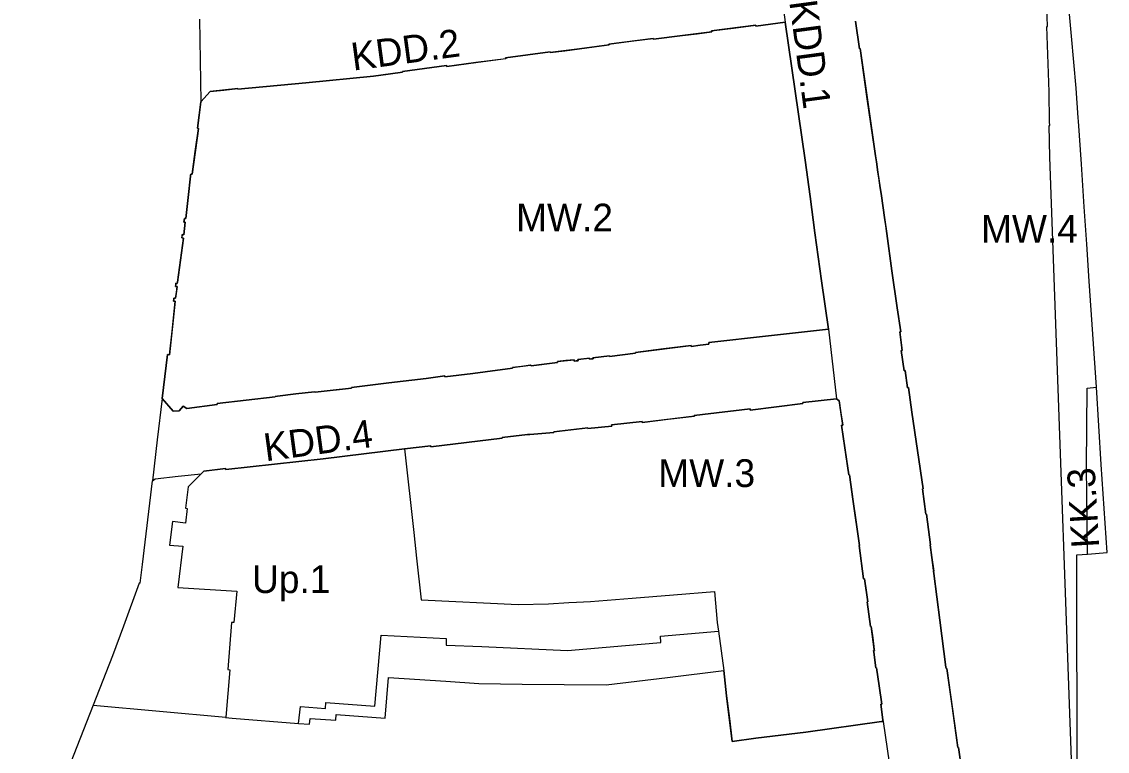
# Model space of a CAD drawing. Extents: x 7423893 to 7425332, y 5547241 to 5548246.
# Drawn here: x 7424450.7 to 7424646.4, y 5547880.1 to 5548011.5 of the extents above; entities that cross this region are included whole.
import ezdxf

# ---------------------------------------------------------------- set-up
doc = ezdxf.new("R2010")
doc.units = 0
for name, color, linetype in [('linie rozgraniczające', 7, 'Continuous'), ('nieprzekraczalne linie zabudowy', 7, 'Continuous'), ('obowiazujace linie zabudowy', 7, 'Continuous'), ('przeznaczenia terenów', 7, 'Continuous')]:
    doc.layers.add(name, color=color, linetype=linetype)

msp = doc.modelspace()

# ---------------------------------------------------------------- linework, layer by layer
at = {"layer": 'linie rozgraniczające'}
for p, q in [((7424586.51, 5548024.42), (7424588.29, 5548011.39)), ((7424596.1, 5547956.13), (7424597.56, 5547943.58))]:
    msp.add_line(p, q, dxfattribs=at)
for points in [[(7424641.11, 5547994.19), (7424640.74, 5547999.53), (7424639.91, 5548008.88), (7424639.08, 5548018.22)], [(7424482.78, 5548011.96), (7424482.88, 5548004.5), (7424482.99, 5547997.04)], [(7424588.29, 5548011.39), (7424590.09, 5547998.96), (7424591.9, 5547986.54), (7424592.79, 5547980), (7424593.67, 5547973.47), (7424594.88, 5547964.8), (7424596.1, 5547956.13), (7424585.32, 5547954.92), (7424574.54, 5547953.71), (7424574.57, 5547953.41), (7424572.98, 5547953.21), (7424571.39, 5547953.01), (7424571.37, 5547953.16), (7424566.35, 5547952.54), (7424561.33, 5547951.92), (7424561.34, 5547951.85), (7424561.35, 5547951.78), (7424559.01, 5547951.49), (7424556.67, 5547951.2), (7424556.66, 5547951.29), (7424555.17, 5547951.13), (7424553.67, 5547950.97), (7424553.68, 5547950.88), (7424553.69, 5547950.79), (7424553.38, 5547950.75), (7424553.07, 5547950.72), (7424553.06, 5547950.81), (7424553.05, 5547950.9), (7424552, 5547950.79), (7424550.96, 5547950.67), (7424550.99, 5547950.43), (7424550.64, 5547950.39), (7424550.29, 5547950.35), (7424550.26, 5547950.59), (7424548.77, 5547950.44), (7424547.27, 5547950.28), (7424547.3, 5547950.08), (7424544.9, 5547949.79), (7424542.5, 5547949.49), (7424542.48, 5547949.6), (7424542.43, 5547949.6), (7424540.79, 5547949.4), (7424539.14, 5547949.19), (7424539.15, 5547949.06), (7424534.22, 5547948.42), (7424531.99, 5547948.14), (7424526.97, 5547947.53), (7424526.95, 5547947.68), (7424523.63, 5547947.25), (7424516.9, 5547946.43), (7424510.16, 5547945.61), (7424510.17, 5547945.51), (7424506.87, 5547945.12), (7424503.57, 5547944.73), (7424503.49, 5547944.82), (7424500.13, 5547944.43), (7424496.78, 5547944.04), (7424496.4, 5547944), (7424496.41, 5547943.94), (7424491.17, 5547943.32), (7424485.94, 5547942.69), (7424485.96, 5547942.53), (7424480.46, 5547941.83), (7424479.8, 5547942.21), (7424479.08, 5547941.42), (7424478.01, 5547941.35), (7424476.01, 5547943.62)], [(7424482.99, 5547997.04), (7424484.67, 5547998.89), (7424487.16, 5547999.17), (7424489.64, 5547999.46), (7424489.66, 5547999.3), (7424501.9, 5548000.49), (7424514.13, 5548001.67), (7424516.75, 5548002.01), (7424519.36, 5548002.36), (7424519.34, 5548002.52), (7424523.31, 5548003.04), (7424527.28, 5548003.57), (7424527.3, 5548003.42), (7424532.56, 5548004.11), (7424537.94, 5548004.82), (7424537.92, 5548004.97), (7424541.92, 5548005.51), (7424545.93, 5548006.05), (7424545.95, 5548005.9), (7424548.6, 5548006.25), (7424551.25, 5548006.59), (7424553.91, 5548006.94), (7424556.56, 5548007.29), (7424556.54, 5548007.43), (7424560.54, 5548007.94), (7424564.53, 5548008.45), (7424564.55, 5548008.3), (7424569.81, 5548008.98), (7424572.44, 5548009.32), (7424575.06, 5548009.66), (7424575.04, 5548009.82), (7424579.02, 5548010.34), (7424582.99, 5548010.86), (7424583.01, 5548010.7), (7424588.29, 5548011.39)], [(7424620.66, 5547872.83), (7424619.56, 5547880.75), (7424619.45, 5547880.74), (7424618.46, 5547887.87), (7424617.47, 5547895), (7424617.31, 5547894.98), (7424617.27, 5547895.26), (7424616.19, 5547903.69), (7424616.19, 5547903.69), (7424615.1, 5547912.11), (7424615.05, 5547912.5), (7424615.07, 5547912.5), (7424615.08, 5547912.51), (7424615.06, 5547912.68), (7424614.75, 5547914.98), (7424614.45, 5547917.28), (7424614.49, 5547917.29), (7424614.52, 5547917.29), (7424614.15, 5547920.03), (7424613.77, 5547922.77), (7424613.72, 5547922.76), (7424613.67, 5547922.76), (7424613.04, 5547927.35), (7424613.2, 5547927.38), (7424611.11, 5547941.13), (7424610.52, 5547945.58), (7424610.38, 5547945.57), (7424609.93, 5547948.64), (7424609.76, 5547948.62), (7424609.24, 5547952.27), (7424609.42, 5547952.29), (7424608.98, 5547955.6), (7424609.14, 5547955.62), (7424608.47, 5547959.96), (7424607.54, 5547966.63), (7424606.62, 5547973.31), (7424606.42, 5547974.74), (7424606.26, 5547975.81), (7424605.58, 5547980.54), (7424605.43, 5547981.54), (7424605.17, 5547983.37), (7424605.02, 5547984.39), (7424604.74, 5547986.24), (7424604.6, 5547987.32), (7424604.42, 5547988.59), (7424603.11, 5547997.61), (7424601.8, 5548006.62), (7424601.7, 5548006.6), (7424600.96, 5548011.55)], [(7424476.01, 5547943.62), (7424477.01, 5547951.52), (7424477.35, 5547951.48), (7424477.87, 5547956.31), (7424478.38, 5547961.14), (7424478.24, 5547961.16), (7424478.09, 5547961.17), (7424478.12, 5547961.44), (7424478.15, 5547961.71), (7424478.29, 5547961.7), (7424478.44, 5547961.68), (7424478.58, 5547962.72), (7424478.71, 5547963.76), (7424478.58, 5547963.78), (7424478.44, 5547963.79), (7424478.46, 5547964.08), (7424478.49, 5547964.36), (7424478.61, 5547964.34), (7424478.73, 5547964.32), (7424478.77, 5547964.57), (7424479.31, 5547968.54), (7424479.85, 5547972.52), (7424479.71, 5547972.54), (7424479.57, 5547972.56), (7424479.61, 5547972.86), (7424479.64, 5547973.15), (7424479.78, 5547973.13), (7424479.92, 5547973.12), (7424480.05, 5547974.24), (7424480.19, 5547975.36), (7424480.07, 5547975.38), (7424479.94, 5547975.39), (7424479.98, 5547975.71), (7424480.02, 5547976.04), (7424480.15, 5547976.03), (7424480.27, 5547976.01), (7424480.7, 5547979.83), (7424481.13, 5547983.66), (7424481.16, 5547983.84), (7424481.18, 5547984.03), (7424481.3, 5547984.01), (7424481.43, 5547984), (7424482, 5547988.13), (7424482.56, 5547992.26), (7424482.46, 5547992.27), (7424482.37, 5547992.28), (7424482.68, 5547994.66), (7424482.99, 5547997.04)], [(7424640.9, 5547851.91), (7424640.96, 5547859.51), (7424641.01, 5547867.11), (7424640.96, 5547875.45), (7424640.92, 5547883.78), (7424640.91, 5547890.83), (7424640.89, 5547897.87), (7424640.87, 5547906.66), (7424640.85, 5547915.45), (7424642.77, 5547915.6), (7424646.36, 5547915.88), (7424645.82, 5547923.81), (7424645.28, 5547931.74), (7424644.86, 5547938.7), (7424644.43, 5547945.66), (7424643.77, 5547955.2), (7424643.1, 5547964.73), (7424642.66, 5547971.42), (7424642.22, 5547978.12), (7424641.69, 5547985.83), (7424641.15, 5547993.55), (7424641.11, 5547994.19)], [(7424642.77, 5547915.6), (7424642.61, 5547931.44), (7424642.76, 5547945.46), (7424644.43, 5547945.66)], [(7424476.01, 5547943.62), (7424475.14, 5547936.2), (7424474.27, 5547928.77)], [(7424474.27, 5547928.77), (7424474.74, 5547929.16), (7424478.89, 5547929.61), (7424483.04, 5547930.06), (7424483.51, 5547930.53), (7424487.46, 5547931.01), (7424487.49, 5547930.82), (7424505.04, 5547932.74), (7424519.71, 5547934.58), (7424524.45, 5547935.07), (7424524.46, 5547934.93), (7424530.89, 5547935.7), (7424537.32, 5547936.46), (7424537.31, 5547936.57), (7424541.84, 5547937.13), (7424541.98, 5547937.13), (7424542.29, 5547937.14), (7424546.6, 5547937.48), (7424546.59, 5547937.63), (7424552.75, 5547938.34), (7424552.76, 5547938.19), (7424557.05, 5547938.66), (7424557.04, 5547938.75), (7424557.02, 5547938.85), (7424562.52, 5547939.47), (7424562.53, 5547939.32), (7424567.24, 5547939.87), (7424571.95, 5547940.41), (7424571.93, 5547940.58), (7424577.44, 5547941.2), (7424577.99, 5547941.25), (7424579.99, 5547941.49), (7424581.99, 5547941.73), (7424582.02, 5547941.54), (7424586.77, 5547942.13), (7424591.51, 5547942.72), (7424591.49, 5547942.88), (7424597.56, 5547943.58), (7424598.03, 5547943.22), (7424598.35, 5547941.03), (7424598.67, 5547938.83), (7424598.47, 5547938.8), (7424599.12, 5547934.33), (7424599.76, 5547929.86), (7424599.9, 5547929.88), (7424600.21, 5547927.69), (7424600.53, 5547925.5), (7424601.12, 5547921.33), (7424601.72, 5547917.17), (7424601.62, 5547917.15), (7424602.45, 5547911.15), (7424602.63, 5547911.17), (7424602.91, 5547909.09), (7424603.18, 5547907.02), (7424603.13, 5547907.01), (7424603.08, 5547907), (7424603.38, 5547904.76), (7424603.67, 5547902.53), (7424603.75, 5547902.54), (7424603.82, 5547902.55), (7424604.08, 5547900.49), (7424604.35, 5547898.42), (7424604.38, 5547898.23), (7424604.23, 5547898.21), (7424604.26, 5547897.95), (7424604.45, 5547896.53), (7424604.63, 5547895.11), (7424604.78, 5547895.13), (7424605.25, 5547891.86), (7424605.72, 5547888.58), (7424605.56, 5547888.56), (7424605.93, 5547885.74), (7424605.97, 5547885.46)], [(7424519.71, 5547934.58), (7424521.37, 5547919.51), (7424521.87, 5547914.86), (7424522.72, 5547907.35), (7424540.2, 5547906.53), (7424545.64, 5547906.65), (7424549.3, 5547906.86), (7424550.69, 5547906.94), (7424553.24, 5547907.09), (7424560.72, 5547907.68), (7424568.15, 5547908.26), (7424575.58, 5547908.85), (7424576.06, 5547903.26), (7424576.26, 5547901.72), (7424576.75, 5547898.19), (7424577.23, 5547894.65)], [(7424472.03, 5547910.35), (7424472.22, 5547911.83), (7424472.46, 5547913.75), (7424474.27, 5547928.77)], [(7424472.03, 5547910.35), (7424471.85, 5547910.38), (7424469.05, 5547902.62), (7424467.1, 5547897.3), (7424450.71, 5547855.6)], [(7424463.6, 5547888.39), (7424487.47, 5547886.26), (7424487.46, 5547886.16), (7424488.65, 5547886.07), (7424500.61, 5547885.12), (7424502.6, 5547884.96), (7424502.72, 5547886.02), (7424507.34, 5547885.68), (7424507.41, 5547886.71), (7424516.19, 5547886.05), (7424516.83, 5547893.38), (7424527.16, 5547892.7), (7424533.1, 5547892.31), (7424540.9, 5547892.17), (7424556.02, 5547892.05), (7424567.08, 5547893.35), (7424577.23, 5547894.65)], [(7424578.75, 5547881.84), (7424577.76, 5547890.1), (7424577.23, 5547894.65)], [(7424605.97, 5547885.46), (7424605.69, 5547885.43), (7424592.01, 5547883.52), (7424583, 5547882.44), (7424578.75, 5547881.84)], [(7424605.97, 5547885.46), (7424607.07, 5547878.07), (7424608.16, 5547870.67)]]:
    msp.add_lwpolyline(points, dxfattribs=at)
at = {"layer": 'nieprzekraczalne linie zabudowy'}
for points in [[(7424640.9, 5547851.91), (7424640.9, 5547851.91), (7424635.99, 5547987.05), (7424635.89, 5547992.77), (7424635.98, 5547992.77), (7424635.97, 5547993.45), (7424635.97, 5547993.45), (7424635.91, 5547998.82), (7424635.47, 5548010.62), (7424635.61, 5548010.62), (7424635.37, 5548017.85)], [(7424515.47, 5547900.97), (7424527.22, 5547900.4), (7424527.2, 5547899.21), (7424533.62, 5547898.94), (7424533.62, 5547898.94), (7424549.05, 5547898.23), (7424559.54, 5547899.13), (7424559.54, 5547899.13), (7424559.54, 5547899.13), (7424565.88, 5547899.66), (7424565.83, 5547900.83), (7424576.26, 5547901.72), (7424577.23, 5547894.65), (7424577.76, 5547890.1)], [(7424577.76, 5547890.1), (7424578.25, 5547885.97), (7424578.75, 5547881.84)], [(7424578.75, 5547881.84), (7424583, 5547882.44), (7424592.01, 5547883.52)]]:
    msp.add_lwpolyline(points, dxfattribs=at)
at = {"layer": 'obowiazujace linie zabudowy'}
for points in [[(7424476.01, 5547943.62), (7424478.01, 5547941.35), (7424479.08, 5547941.42), (7424479.8, 5547942.21), (7424480.46, 5547941.83), (7424485.96, 5547942.53), (7424485.94, 5547942.69), (7424496.41, 5547943.94), (7424496.4, 5547944), (7424496.78, 5547944.04), (7424500.13, 5547944.43), (7424503.49, 5547944.82), (7424503.57, 5547944.73), (7424510.17, 5547945.51), (7424510.16, 5547945.61), (7424516.9, 5547946.43), (7424523.63, 5547947.25), (7424526.95, 5547947.68), (7424526.97, 5547947.53), (7424531.99, 5547948.14), (7424534.22, 5547948.42), (7424539.15, 5547949.06), (7424539.15, 5547949.06), (7424539.14, 5547949.19), (7424542.43, 5547949.6), (7424542.48, 5547949.6), (7424542.5, 5547949.49), (7424547.3, 5547950.08), (7424547.27, 5547950.25), (7424547.27, 5547950.28), (7424550.26, 5547950.59), (7424550.29, 5547950.35), (7424550.99, 5547950.43), (7424550.96, 5547950.67), (7424553.05, 5547950.9), (7424553.07, 5547950.72), (7424553.69, 5547950.79), (7424553.67, 5547950.97), (7424556.66, 5547951.29), (7424556.67, 5547951.2), (7424561.35, 5547951.78), (7424561.35, 5547951.78), (7424561.33, 5547951.92), (7424571.37, 5547953.16), (7424571.39, 5547953.01), (7424571.39, 5547953.01), (7424572.98, 5547953.21), (7424574.57, 5547953.41), (7424574.54, 5547953.71), (7424585.32, 5547954.92), (7424596.1, 5547956.13), (7424594.88, 5547964.8), (7424593.67, 5547973.47), (7424592.79, 5547980), (7424591.9, 5547986.54), (7424590.09, 5547998.96), (7424588.29, 5548011.39), (7424585.65, 5548011.04), (7424583.01, 5548010.7), (7424582.99, 5548010.86), (7424575.04, 5548009.82), (7424575.06, 5548009.66), (7424569.81, 5548008.98), (7424564.55, 5548008.3), (7424564.53, 5548008.45), (7424556.54, 5548007.43), (7424556.56, 5548007.29), (7424551.25, 5548006.59), (7424545.95, 5548005.9), (7424545.93, 5548006.05), (7424537.92, 5548004.97), (7424537.94, 5548004.8), (7424532.56, 5548004.11), (7424527.3, 5548003.42), (7424527.28, 5548003.57), (7424519.34, 5548002.52), (7424519.36, 5548002.36), (7424514.13, 5548001.67), (7424501.9, 5548000.49), (7424489.66, 5547999.3), (7424489.64, 5547999.46), (7424484.67, 5547998.89), (7424482.99, 5547997.04)], [(7424600.96, 5548011.55), (7424601.7, 5548006.6), (7424601.8, 5548006.62), (7424604.42, 5547988.59), (7424604.6, 5547987.32), (7424604.74, 5547986.24), (7424605.02, 5547984.39), (7424605.43, 5547981.54), (7424605.58, 5547980.54), (7424606.26, 5547975.81), (7424606.62, 5547973.31), (7424607.54, 5547966.63), (7424608.47, 5547959.96), (7424609.14, 5547955.62), (7424608.98, 5547955.6), (7424609.42, 5547952.29), (7424609.24, 5547952.27), (7424609.76, 5547948.62), (7424609.93, 5547948.64), (7424610.38, 5547945.57), (7424610.52, 5547945.58), (7424611.11, 5547941.13), (7424612.16, 5547934.25), (7424613.2, 5547927.38), (7424613.04, 5547927.35), (7424613.36, 5547925.05), (7424613.67, 5547922.76), (7424613.77, 5547922.77), (7424614.52, 5547917.29), (7424614.45, 5547917.28), (7424614.75, 5547914.98), (7424615.08, 5547912.51), (7424615.05, 5547912.51), (7424615.1, 5547912.11), (7424615.1, 5547912.11), (7424616.19, 5547903.69), (7424617.27, 5547895.26), (7424617.31, 5547894.98), (7424617.47, 5547895), (7424619.45, 5547880.74), (7424619.56, 5547880.75), (7424621.75, 5547864.91)], [(7424482.99, 5547997.04), (7424482.37, 5547992.28), (7424482.56, 5547992.26), (7424481.43, 5547984), (7424481.18, 5547984.03), (7424481.13, 5547983.66), (7424480.7, 5547979.83), (7424480.27, 5547976.01), (7424480.02, 5547976.04), (7424479.94, 5547975.39), (7424480.19, 5547975.36), (7424479.92, 5547973.12), (7424479.64, 5547973.15), (7424479.57, 5547972.56), (7424479.85, 5547972.52), (7424478.77, 5547964.57), (7424478.73, 5547964.32), (7424478.49, 5547964.36), (7424478.44, 5547963.79), (7424478.71, 5547963.76), (7424478.44, 5547961.68), (7424478.15, 5547961.71), (7424478.09, 5547961.17), (7424478.38, 5547961.14), (7424477.35, 5547951.48), (7424477.01, 5547951.52), (7424476.01, 5547943.62)], [(7424592.01, 5547883.52), (7424605.69, 5547885.43), (7424605.97, 5547885.46), (7424605.93, 5547885.74), (7424605.56, 5547888.56), (7424605.72, 5547888.58), (7424605.25, 5547891.86), (7424604.78, 5547895.13), (7424604.63, 5547895.11), (7424604.26, 5547897.95), (7424604.23, 5547898.21), (7424604.38, 5547898.23), (7424604.35, 5547898.42), (7424603.82, 5547902.55), (7424603.67, 5547902.53), (7424603.08, 5547907), (7424603.18, 5547907.02), (7424602.63, 5547911.17), (7424602.45, 5547911.15), (7424601.62, 5547917.15), (7424601.72, 5547917.17), (7424600.53, 5547925.5), (7424599.9, 5547929.88), (7424599.76, 5547929.86), (7424598.47, 5547938.8), (7424598.67, 5547938.83), (7424598.03, 5547943.22), (7424597.56, 5547943.58), (7424591.49, 5547942.88), (7424591.51, 5547942.72), (7424582.02, 5547941.54), (7424581.99, 5547941.73), (7424577.99, 5547941.25), (7424577.44, 5547941.2), (7424571.93, 5547940.58), (7424571.95, 5547940.41), (7424562.53, 5547939.32), (7424562.52, 5547939.47), (7424562.51, 5547939.47), (7424557.02, 5547938.85), (7424557.05, 5547938.66), (7424552.76, 5547938.19), (7424552.75, 5547938.34), (7424546.59, 5547937.63), (7424546.6, 5547937.48), (7424542.29, 5547937.14), (7424541.98, 5547937.13), (7424541.84, 5547937.13), (7424537.31, 5547936.57), (7424537.32, 5547936.46), (7424524.46, 5547934.93), (7424524.45, 5547935.07), (7424524.44, 5547935.07), (7424519.71, 5547934.58), (7424512.38, 5547933.66), (7424505.04, 5547932.74), (7424496.27, 5547931.78), (7424487.49, 5547930.82), (7424487.46, 5547931.01), (7424485.49, 5547930.77), (7424483.51, 5547930.53), (7424483.04, 5547930.06), (7424480.68, 5547927.73), (7424480.23, 5547923.84), (7424480.54, 5547923.81), (7424480.2, 5547921.17), (7424477.87, 5547921.46), (7424477.34, 5547917.23), (7424479.74, 5547917.04), (7424478.86, 5547909.61), (7424489.48, 5547908.94), (7424488.92, 5547903.27), (7424488.52, 5547903.3), (7424487.83, 5547894.8), (7424488.23, 5547894.77), (7424487.47, 5547886.26), (7424487.46, 5547886.16), (7424488.65, 5547886.07), (7424500.61, 5547885.12), (7424500.94, 5547888.16), (7424505.48, 5547887.82), (7424505.55, 5547888.85), (7424514.37, 5547888.19), (7424515.47, 5547900.97)]]:
    msp.add_lwpolyline(points, dxfattribs=at)

# ---------------------------------------------------------------- texts
at = {"layer": 'przeznaczenia terenów'}
for s, rotation, p in [('KDD.1', 277.6607, (7424589.03, 5548015.08)), ('KDD.2', 7.6607, (7424510.44, 5548002.65)), ('KDD.4', 7.6607, (7424494.68, 5547932.29)), ('KK.3', 93.3727, (7424644.93, 5547916.84))]:
    msp.add_text(s, height=5, rotation=rotation, dxfattribs=at).set_placement(p)
for s, p in [('MW.2', (7424539.81, 5547973.7)), ('MW.4', (7424623.61, 5547971.67)), ('MW.3', (7424565.44, 5547927.68)), ('Up.1', (7424492.22, 5547908.59))]:
    msp.add_text(s, height=5, dxfattribs=at).set_placement(p)

doc.saveas('drawing.dxf')
